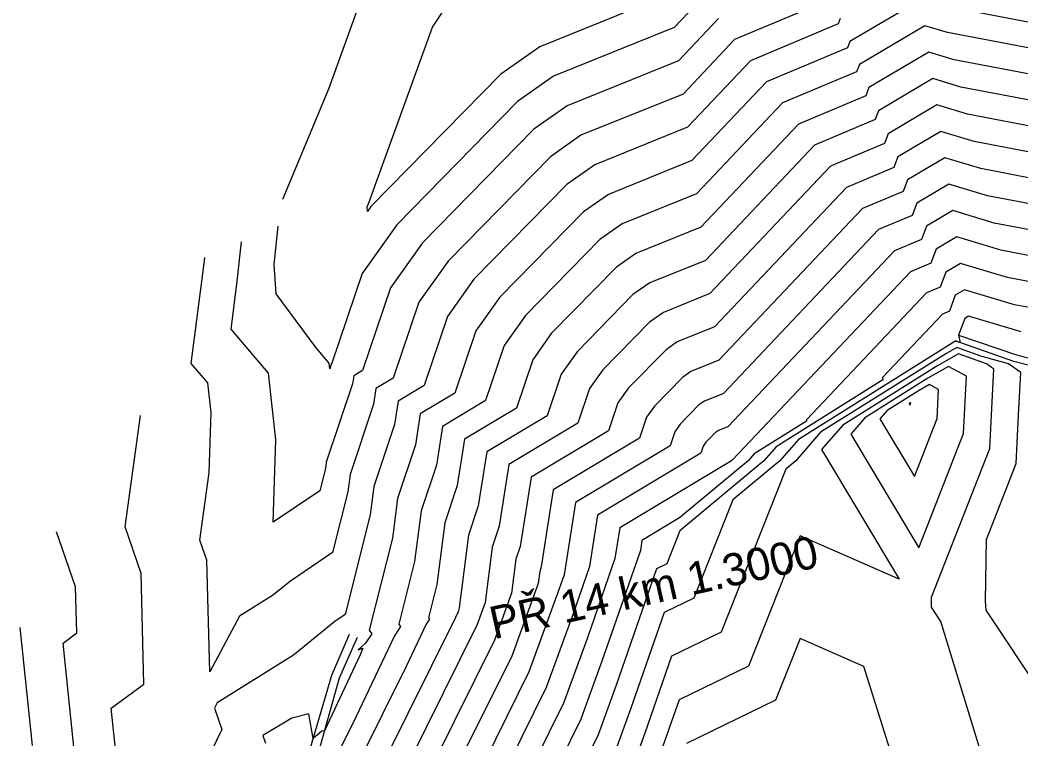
# Model space of a CAD drawing. Extents: x -549394 to -546608, y -1037055 to -1033629.
# Drawn here: x -548857.3 to -548577.2, y -1034124.2 to -1033923 of the extents above; entities that cross this region are included whole.
import ezdxf

# ---------------------------------------------------------------- set-up
doc = ezdxf.new("R2010")
doc.units = 0
for name, color, linetype in [('hlavni_vrst', 7, 'Continuous'), ('hrana_L', 7, 'Continuous'), ('norm_vrst', 7, 'Continuous'), ('x_popis_pricne_rezy_C21', 7, 'Continuous')]:
    doc.layers.add(name, color=color, linetype=linetype)

msp = doc.modelspace()

# ---------------------------------------------------------------- linework, layer by layer
at = {"layer": 'hlavni_vrst'}
for p, q in [((-548627.8, -1033922.53), (-548628.37, -1033924.06)), ((-548628.37, -1033924.06), (-548652.86, -1033934.37)), ((-548652.86, -1033934.37), (-548670.52, -1033953.01)), ((-548600.78, -1033946.76), (-548614.38, -1033954.83)), ((-548592.15, -1033949.35), (-548600.78, -1033946.76)), ((-548540.66, -1033959.22), (-548592.15, -1033949.35)), ((-548670.52, -1033953.01), (-548696.49, -1033963.52)), ((-548614.38, -1033954.83), (-548615.41, -1033957.58)), ((-548615.41, -1033957.58), (-548630.48, -1033963.92)), ((-548696.49, -1033963.52), (-548704.26, -1033968.98)), ((-548630.48, -1033963.92), (-548664.24, -1033999.57)), ((-548704.26, -1033968.98), (-548730.27, -1033995.53)), ((-548595.2, -1033983.71), (-548600.96, -1033987.12)), ((-548582.81, -1033987.44), (-548595.2, -1033983.71)), ((-548600.96, -1033987.12), (-548602.44, -1033991.09)), ((-548508.87, -1034001.61), (-548582.81, -1033987.44)), ((-548602.44, -1033991.09), (-548608.09, -1033993.47)), ((-548730.27, -1033995.53), (-548737.72, -1034006)), ((-548608.09, -1033993.47), (-548657.97, -1034046.13)), ((-548664.24, -1033999.57), (-548677.27, -1034004.84)), ((-548737.72, -1034006), (-548744.24, -1034025.33)), ((-548677.27, -1034004.84), (-548681.16, -1034007.58)), ((-548681.16, -1034007.58), (-548694.21, -1034020.89)), ((-548594.72, -1034016.44), (-548600.73, -1034019.84)), ((-548586.9, -1034019.27), (-548594.72, -1034016.44)), ((-548694.21, -1034020.89), (-548697.94, -1034026.14)), ((-548600.73, -1034019.84), (-548627.1, -1034036.36)), ((-548584.85, -1034020.69), (-548586.9, -1034019.27)), ((-548585.34, -1034031.77), (-548584.85, -1034020.69)), ((-548744.24, -1034025.33), (-548751.51, -1034029.69)), ((-548697.94, -1034026.14), (-548701.21, -1034035.84)), ((-548751.51, -1034029.69), (-548752.53, -1034036.21)), ((-548585.94, -1034042.9), (-548585.34, -1034031.77)), ((-548827.91, -1034064.82), (-548823.56, -1034033.65)), ((-548752.53, -1034036.21), (-548758.32, -1034053.57)), ((-548701.21, -1034035.84), (-548720.49, -1034047.4)), ((-548627.1, -1034036.36), (-548633.02, -1034043.25)), ((-548633.02, -1034043.25), (-548611.26, -1034079.53)), ((-548602.21, -1034084.51), (-548585.94, -1034042.9)), ((-548658.19, -1034046.35), (-548689.46, -1034065.1)), ((-548658.17, -1034046.29), (-548658.19, -1034046.35)), ((-548658.15, -1034046.26), (-548658.17, -1034046.29)), ((-548658.07, -1034046.18), (-548658.15, -1034046.26)), ((-548658.05, -1034046.16), (-548658.07, -1034046.18)), ((-548657.97, -1034046.13), (-548658.05, -1034046.16)), ((-548720.49, -1034047.4), (-548723.2, -1034064.67)), ((-548758.32, -1034053.57), (-548759.35, -1034061.54)), ((-548759.35, -1034061.54), (-548766.36, -1034089.43)), ((-548823.39, -1034077.91), (-548827.91, -1034064.82)), ((-548723.2, -1034064.67), (-548725.16, -1034070.55)), ((-548689.46, -1034065.1), (-548690.82, -1034073.74)), ((-548638.98, -1034067.36), (-548653.49, -1034103.86)), ((-548611.26, -1034079.53), (-548638.98, -1034067.36)), ((-548725.16, -1034070.55), (-548727.15, -1034086.06)), ((-548690.82, -1034073.74), (-548698.45, -1034095.69)), ((-548822.61, -1034108.85), (-548823.39, -1034077.91)), ((-548602.24, -1034087.01), (-548602.21, -1034084.51)), ((-548727.15, -1034086.06), (-548729.39, -1034092.21)), ((-548602.22, -1034087.38), (-548602.24, -1034087.01)), ((-548599.61, -1034091.31), (-548602.22, -1034087.38)), ((-548766.36, -1034089.43), (-548769.21, -1034091.35)), ((-548769.21, -1034091.35), (-548780.77, -1034100.82)), ((-548729.39, -1034092.21), (-548749.87, -1034133.46)), ((-548583.87, -1034143.01), (-548599.61, -1034091.31)), ((-548698.45, -1034095.69), (-548705.2, -1034114.25)), ((-548780.77, -1034100.82), (-548802.13, -1034114.16)), ((-548653.49, -1034103.86), (-548672.9, -1034113.25)), ((-548831.8, -1034115.63), (-548822.61, -1034108.85)), ((-548672.9, -1034113.25), (-548678.51, -1034129.39)), ((-548830.24, -1034130.51), (-548831.8, -1034115.63)), ((-548802.13, -1034114.16), (-548802.91, -1034115.6)), ((-548802.91, -1034115.6), (-548800.87, -1034121.57)), ((-548705.2, -1034114.25), (-548717.77, -1034139.57)), ((-548800.87, -1034121.57), (-548805.2, -1034130.59))]:
    msp.add_line(p, q, dxfattribs=at)
at = {"layer": 'hrana_L'}
for p, q in [((-548579.25, -1034018.6), (-548595.61, -1034012.8)), ((-548594.66, -1034011.2), (-548578.47, -1034016.69)), ((-548578.47, -1034016.69), (-548560.81, -1034021.29)), ((-548561.83, -1034023.04), (-548579.25, -1034018.6)), ((-548765.24, -1034094.98), (-548770.17, -1034106.46)), ((-548763, -1034095.87), (-548768.02, -1034107.25)), ((-548770.17, -1034106.46), (-548776.76, -1034129.09)), ((-548768.02, -1034107.25), (-548774.07, -1034128.86))]:
    msp.add_line(p, q, dxfattribs=at)
at = {"layer": 'norm_vrst'}
for p, q in [((-548770.93, -1033942.25), (-548761.43, -1033916.07)), ((-548741.85, -1033924.97), (-548736.86, -1033917.29)), ((-548675.54, -1033915.76), (-548711.87, -1033930.47)), ((-548666.3, -1033916.64), (-548674.29, -1033925.07)), ((-548630.97, -1033917.36), (-548657.34, -1033928.46)), ((-548605.25, -1033917.2), (-548625.12, -1033928.99)), ((-548566.09, -1033925.31), (-548599.62, -1033918.89)), ((-548661.82, -1033922.55), (-548673.03, -1033934.39)), ((-548759.67, -1033974.12), (-548741.85, -1033924.97)), ((-548674.29, -1033925.07), (-548708.03, -1033938.73)), ((-548604.13, -1033924.59), (-548622.43, -1033935.45)), ((-548597.75, -1033926.5), (-548604.13, -1033924.59)), ((-548657.34, -1033928.46), (-548671.78, -1033943.7)), ((-548559.73, -1033933.79), (-548597.75, -1033926.5)), ((-548711.87, -1033930.47), (-548722.73, -1033938.1)), ((-548625.78, -1033930.77), (-548648.39, -1033940.28)), ((-548625.12, -1033928.99), (-548625.78, -1033930.77)), ((-548673.03, -1033934.39), (-548704.18, -1033946.99)), ((-548603.01, -1033931.98), (-548619.75, -1033941.91)), ((-548595.89, -1033934.12), (-548603.01, -1033931.98)), ((-548553.37, -1033942.27), (-548595.89, -1033934.12)), ((-548622.43, -1033935.45), (-548623.19, -1033937.47)), ((-548722.73, -1033938.1), (-548759.11, -1033975.23)), ((-548708.03, -1033938.73), (-548718.11, -1033945.82)), ((-548623.19, -1033937.47), (-548643.91, -1033946.19)), ((-548601.9, -1033939.37), (-548617.07, -1033948.37)), ((-548594.02, -1033941.74), (-548601.9, -1033939.37)), ((-548783.78, -1033973.1), (-548770.93, -1033942.25)), ((-548648.39, -1033940.28), (-548669.27, -1033962.32)), ((-548619.75, -1033941.91), (-548620.59, -1033944.17)), ((-548547.01, -1033950.75), (-548594.02, -1033941.74)), ((-548671.78, -1033943.7), (-548700.34, -1033955.26)), ((-548620.59, -1033944.17), (-548639.43, -1033952.1)), ((-548718.11, -1033945.82), (-548751.9, -1033980.31)), ((-548704.18, -1033946.99), (-548713.49, -1033953.54)), ((-548643.91, -1033946.19), (-548668.01, -1033971.63)), ((-548617.07, -1033948.37), (-548618, -1033950.87)), ((-548618, -1033950.87), (-548634.96, -1033958.01)), ((-548713.49, -1033953.54), (-548744.69, -1033985.38)), ((-548639.43, -1033952.1), (-548666.75, -1033980.95)), ((-548700.34, -1033955.26), (-548708.87, -1033961.26)), ((-548599.67, -1033954.15), (-548611.7, -1033961.29)), ((-548590.28, -1033956.97), (-548599.67, -1033954.15)), ((-548634.96, -1033958.01), (-548665.5, -1033990.26)), ((-548534.3, -1033967.7), (-548590.28, -1033956.97)), ((-548708.87, -1033961.26), (-548737.48, -1033990.45)), ((-548669.27, -1033962.32), (-548692.65, -1033971.79)), ((-548611.7, -1033961.29), (-548612.81, -1033964.28)), ((-548598.55, -1033961.54), (-548609.01, -1033967.75)), ((-548588.41, -1033964.59), (-548598.55, -1033961.54)), ((-548612.81, -1033964.28), (-548626, -1033969.83)), ((-548527.94, -1033976.18), (-548588.41, -1033964.59)), ((-548609.01, -1033967.75), (-548610.22, -1033970.98)), ((-548626, -1033969.83), (-548662.99, -1034008.88)), ((-548597.44, -1033968.93), (-548606.33, -1033974.21)), ((-548586.54, -1033972.2), (-548597.44, -1033968.93)), ((-548692.65, -1033971.79), (-548699.64, -1033976.7)), ((-548668.01, -1033971.63), (-548688.8, -1033980.05)), ((-548610.22, -1033970.98), (-548621.52, -1033975.74)), ((-548521.58, -1033984.65), (-548586.54, -1033972.2)), ((-548760.14, -1033975.25), (-548759.67, -1033974.12)), ((-548760.04, -1033976.54), (-548760.14, -1033975.25)), ((-548759.11, -1033975.23), (-548760.04, -1033976.54)), ((-548621.52, -1033975.74), (-548661.73, -1034018.19)), ((-548606.33, -1033974.21), (-548607.63, -1033977.69)), ((-548596.32, -1033976.32), (-548603.65, -1033980.67)), ((-548584.67, -1033979.82), (-548596.32, -1033976.32)), ((-548699.64, -1033976.7), (-548723.05, -1034000.6)), ((-548607.63, -1033977.69), (-548617.05, -1033981.65)), ((-548786.2, -1033991.45), (-548785.02, -1033980.7)), ((-548751.9, -1033980.31), (-548761.58, -1033993.91)), ((-548688.8, -1033980.05), (-548695.02, -1033984.42)), ((-548666.75, -1033980.95), (-548684.96, -1033988.31)), ((-548617.05, -1033981.65), (-548660.48, -1034027.51)), ((-548603.65, -1033980.67), (-548605.03, -1033984.39)), ((-548515.22, -1033993.13), (-548584.67, -1033979.82)), ((-548695.02, -1033984.42), (-548715.84, -1034005.67)), ((-548605.03, -1033984.39), (-548612.57, -1033987.56)), ((-548796.62, -1033996.93), (-548795.32, -1033985.1)), ((-548744.69, -1033985.38), (-548753.63, -1033997.94)), ((-548612.57, -1033987.56), (-548659.22, -1034036.82)), ((-548805.97, -1033992.57), (-548805.63, -1033989.5)), ((-548737.48, -1033990.45), (-548745.67, -1034001.97)), ((-548684.96, -1033988.31), (-548690.4, -1033992.14)), ((-548665.5, -1033990.26), (-548681.11, -1033996.58)), ((-548809.39, -1034019.11), (-548805.97, -1033992.57)), ((-548785.58, -1033999.63), (-548786.2, -1033991.45)), ((-548690.4, -1033992.14), (-548708.63, -1034010.74)), ((-548594.09, -1033991.1), (-548598.28, -1033993.58)), ((-548580.94, -1033995.05), (-548594.09, -1033991.1)), ((-548761.58, -1033993.91), (-548770.05, -1034019.02)), ((-548598.28, -1033993.58), (-548599.85, -1033997.79)), ((-548526.36, -1034005.51), (-548580.94, -1033995.05)), ((-548798.24, -1034009.5), (-548796.62, -1033996.93)), ((-548753.63, -1033997.94), (-548761.45, -1034021.12)), ((-548681.11, -1033996.58), (-548685.78, -1033999.86)), ((-548599.85, -1033997.79), (-548603.61, -1033999.38)), ((-548592.97, -1033998.49), (-548595.59, -1034000.04)), ((-548579.07, -1034002.67), (-548592.97, -1033998.49)), ((-548774.44, -1034014.78), (-548785.58, -1033999.63)), ((-548723.05, -1034000.6), (-548729.76, -1034010.03)), ((-548685.78, -1033999.86), (-548701.42, -1034015.82)), ((-548603.61, -1033999.38), (-548637.27, -1034034.91)), ((-548595.59, -1034000.04), (-548597.25, -1034004.5)), ((-548745.67, -1034001.97), (-548752.84, -1034023.23)), ((-548547.43, -1034008.73), (-548579.07, -1034002.67)), ((-548715.84, -1034005.67), (-548721.81, -1034014.06)), ((-548599.14, -1034005.29), (-548615.96, -1034023.06)), ((-548597.25, -1034004.5), (-548599.14, -1034005.29)), ((-548592.91, -1034006.5), (-548594.66, -1034011.2)), ((-548591.86, -1034005.88), (-548592.91, -1034006.5)), ((-548577.2, -1034010.29), (-548591.86, -1034005.88)), ((-548787.78, -1034021.81), (-548798.24, -1034009.5)), ((-548729.76, -1034010.03), (-548735.63, -1034027.43)), ((-548662.99, -1034008.88), (-548673.42, -1034013.11)), ((-548708.63, -1034010.74), (-548713.85, -1034018.09)), ((-548594.66, -1034011.2), (-548594.27, -1034013.28)), ((-548594.66, -1034011.2), (-548594.66, -1034011.2)), ((-548594.66, -1034011.2), (-548594.66, -1034011.2)), ((-548594.66, -1034011.2), (-548594.66, -1034011.2)), ((-548594.66, -1034011.2), (-548594.66, -1034011.2)), ((-548594.66, -1034011.2), (-548594.66, -1034011.2)), ((-548770.82, -1034019.04), (-548774.44, -1034014.78)), ((-548721.81, -1034014.06), (-548727.03, -1034029.53)), ((-548676.54, -1034015.3), (-548686.99, -1034025.96)), ((-548673.42, -1034013.11), (-548676.54, -1034015.3)), ((-548595.73, -1034012.97), (-548639.5, -1034040.41)), ((-548595.15, -1034014.66), (-548598.23, -1034016.4)), ((-548595.59, -1034012.89), (-548595.73, -1034012.97)), ((-548595.27, -1034013), (-548595.59, -1034012.89)), ((-548594.27, -1034013.28), (-548595.27, -1034013)), ((-548588.48, -1034017.08), (-548595.15, -1034014.66)), ((-548713.85, -1034018.09), (-548718.42, -1034031.63)), ((-548701.42, -1034015.82), (-548705.9, -1034022.11)), ((-548661.73, -1034018.19), (-548669.58, -1034021.37)), ((-548598.23, -1034016.4), (-548633.3, -1034038.39)), ((-548580.67, -1034019.2), (-548588.48, -1034017.08)), ((-548804.74, -1034024.58), (-548809.39, -1034019.11)), ((-548770.64, -1034020.65), (-548770.82, -1034019.04)), ((-548770.13, -1034019.13), (-548770.64, -1034020.65)), ((-548770.12, -1034019.07), (-548770.13, -1034019.13)), ((-548770.05, -1034019.02), (-548770.12, -1034019.07)), ((-548761.45, -1034021.12), (-548763.92, -1034022.61)), ((-548597.46, -1034020.01), (-548603.23, -1034023.27)), ((-548592.46, -1034022.69), (-548597.46, -1034020.01)), ((-548577.22, -1034021.65), (-548580.67, -1034019.2)), ((-548785.7, -1034040.5), (-548787.78, -1034021.81)), ((-548763.92, -1034022.61), (-548764.27, -1034024.82)), ((-548752.84, -1034023.23), (-548757.71, -1034026.15)), ((-548705.9, -1034022.11), (-548709.82, -1034033.74)), ((-548671.92, -1034023.02), (-548679.78, -1034031.04)), ((-548669.58, -1034021.37), (-548671.92, -1034023.02)), ((-548615.89, -1034023.73), (-548645.71, -1034042.43)), ((-548603.23, -1034023.27), (-548620.89, -1034034.34)), ((-548615.96, -1034023.06), (-548615.89, -1034023.73)), ((-548593.32, -1034038.72), (-548592.46, -1034022.69)), ((-548577.91, -1034033.56), (-548577.22, -1034021.65)), ((-548803.82, -1034032.89), (-548804.74, -1034024.58)), ((-548764.27, -1034024.82), (-548771.59, -1034046.78)), ((-548757.71, -1034026.15), (-548758.4, -1034030.52)), ((-548686.99, -1034025.96), (-548689.99, -1034030.17)), ((-548605.73, -1034026.7), (-548614.69, -1034032.32)), ((-548602.8, -1034025.05), (-548605.73, -1034026.7)), ((-548600.26, -1034026.41), (-548602.8, -1034025.05)), ((-548600.7, -1034034.54), (-548600.26, -1034026.41)), ((-548735.63, -1034027.43), (-548745.31, -1034033.23)), ((-548727.03, -1034029.53), (-548739.1, -1034036.77)), ((-548665.73, -1034029.63), (-548667.31, -1034030.74)), ((-548660.48, -1034027.51), (-548665.73, -1034029.63)), ((-548758.4, -1034030.52), (-548764.96, -1034050.17)), ((-548718.42, -1034031.63), (-548732.9, -1034040.31)), ((-548689.99, -1034030.17), (-548692.61, -1034037.94)), ((-548679.78, -1034031.04), (-548682.03, -1034034.2)), ((-548667.31, -1034030.74), (-548672.57, -1034036.11)), ((-548614.69, -1034032.32), (-548616.7, -1034034.66)), ((-548608.49, -1034030.3), (-548608.54, -1034030.37)), ((-548608.54, -1034030.37), (-548608.26, -1034030.84)), ((-548608.23, -1034030.14), (-548608.49, -1034030.3)), ((-548608.26, -1034030.84), (-548608.08, -1034030.37)), ((-548608.14, -1034030.09), (-548608.23, -1034030.14)), ((-548608.07, -1034030.13), (-548608.14, -1034030.09)), ((-548608.08, -1034030.37), (-548608.07, -1034030.13)), ((-548804.34, -1034049.67), (-548803.82, -1034032.89)), ((-548745.31, -1034033.23), (-548746.67, -1034041.9)), ((-548709.82, -1034033.74), (-548726.69, -1034043.86)), ((-548682.03, -1034034.2), (-548684, -1034040.04)), ((-548637.23, -1034035.25), (-548651.91, -1034044.45)), ((-548637.27, -1034034.91), (-548637.23, -1034035.25)), ((-548620.89, -1034034.34), (-548624.86, -1034038.95)), ((-548616.7, -1034034.66), (-548607.04, -1034050.77)), ((-548607.04, -1034050.77), (-548600.7, -1034034.54)), ((-548578.25, -1034041.38), (-548577.91, -1034033.56)), ((-548739.1, -1034036.77), (-548740.8, -1034047.59)), ((-548692.61, -1034037.94), (-548714.28, -1034050.94)), ((-548672.57, -1034036.11), (-548674.08, -1034038.23)), ((-548661.89, -1034037.9), (-548662.69, -1034038.46)), ((-548659.22, -1034036.82), (-548661.89, -1034037.9)), ((-548786.42, -1034063.53), (-548785.7, -1034040.5)), ((-548732.9, -1034040.31), (-548734.93, -1034053.28)), ((-548684, -1034040.04), (-548708.08, -1034054.48)), ((-548674.08, -1034038.23), (-548675.4, -1034042.14)), ((-548662.69, -1034038.46), (-548665.36, -1034041.18)), ((-548639.5, -1034040.41), (-548644.65, -1034046.39)), ((-548633.3, -1034038.39), (-548640.18, -1034046.38)), ((-548624.86, -1034038.95), (-548605.82, -1034070.71)), ((-548605.82, -1034070.71), (-548593.32, -1034038.72)), ((-548746.67, -1034041.9), (-548751.69, -1034056.96)), ((-548675.4, -1034042.14), (-548701.87, -1034058.02)), ((-548666.12, -1034042.26), (-548666.79, -1034044.25)), ((-548665.36, -1034041.18), (-548666.12, -1034042.26)), ((-548645.71, -1034042.43), (-548649.12, -1034046.4)), ((-548578.56, -1034047.08), (-548578.25, -1034041.38)), ((-548726.69, -1034043.86), (-548729.07, -1034058.98)), ((-548666.79, -1034044.25), (-548695.67, -1034061.56)), ((-548653.59, -1034046.4), (-548672.74, -1034062.34)), ((-548649.12, -1034046.4), (-548672.65, -1034065.98)), ((-548644.65, -1034046.39), (-548657.81, -1034057.34)), ((-548651.91, -1034044.45), (-548653.59, -1034046.4)), ((-548640.18, -1034046.38), (-548642.98, -1034048.71)), ((-548771.82, -1034048.54), (-548773.37, -1034054.73)), ((-548771.59, -1034046.78), (-548771.82, -1034048.54)), ((-548740.8, -1034047.59), (-548745.06, -1034060.36)), ((-548642.98, -1034048.71), (-548661.11, -1034094.32)), ((-548586.89, -1034068.39), (-548578.56, -1034047.08)), ((-548806.98, -1034068.56), (-548804.34, -1034049.67)), ((-548764.96, -1034050.17), (-548765.58, -1034055.04)), ((-548714.28, -1034050.94), (-548717.33, -1034070.36)), ((-548773.37, -1034054.73), (-548786.42, -1034063.53)), ((-548734.93, -1034053.28), (-548738.43, -1034063.75)), ((-548708.08, -1034054.48), (-548711.47, -1034076.05)), ((-548765.58, -1034055.04), (-548769.87, -1034072.08)), ((-548751.69, -1034056.96), (-548753.11, -1034068.04)), ((-548657.81, -1034057.34), (-548668.72, -1034084.78)), ((-548745.06, -1034060.36), (-548746.88, -1034074.54)), ((-548729.07, -1034058.98), (-548731.79, -1034067.15)), ((-548701.87, -1034058.02), (-548705.05, -1034078.25)), ((-548695.67, -1034061.56), (-548697.94, -1034075.99)), ((-548672.74, -1034062.34), (-548683.26, -1034068.64)), ((-548738.43, -1034063.75), (-548740.64, -1034081.04)), ((-548672.65, -1034065.98), (-548676.34, -1034075.24)), ((-548841.76, -1034081.61), (-548847.06, -1034066.26)), ((-548805.03, -1034074.21), (-548806.98, -1034068.56)), ((-548753.11, -1034068.04), (-548759.59, -1034093.8)), ((-548731.79, -1034067.15), (-548734.41, -1034087.54)), ((-548683.26, -1034068.64), (-548683.71, -1034071.48)), ((-548587.15, -1034085.62), (-548586.89, -1034068.39)), ((-548717.33, -1034070.36), (-548718.53, -1034073.94)), ((-548683.71, -1034071.48), (-548694.46, -1034102.43)), ((-548804.23, -1034105.43), (-548805.03, -1034074.21)), ((-548769.87, -1034072.08), (-548781.63, -1034080.02)), ((-548718.53, -1034073.94), (-548719.74, -1034083.4)), ((-548746.88, -1034074.54), (-548751.29, -1034092.07)), ((-548711.47, -1034076.05), (-548711.89, -1034077.34)), ((-548697.94, -1034075.99), (-548702.44, -1034088.95)), ((-548679.16, -1034076.61), (-548690.47, -1034109.17)), ((-548676.34, -1034075.24), (-548679.16, -1034076.61)), ((-548781.63, -1034080.02), (-548786.62, -1034084.1)), ((-548711.89, -1034077.34), (-548712.33, -1034080.73)), ((-548705.05, -1034078.25), (-548706.43, -1034082.21)), ((-548841.43, -1034094.56), (-548841.76, -1034081.61)), ((-548740.64, -1034081.04), (-548742.98, -1034090.34)), ((-548712.33, -1034080.73), (-548719.72, -1034101.03)), ((-548706.43, -1034082.21), (-548714.88, -1034105.43)), ((-548786.62, -1034084.1), (-548795.84, -1034089.86)), ((-548719.74, -1034083.4), (-548724.55, -1034096.62)), ((-548668.72, -1034084.78), (-548677.07, -1034088.82)), ((-548586.99, -1034088.17), (-548587.15, -1034085.62)), ((-548734.41, -1034087.54), (-548734.68, -1034088.61)), ((-548569.05, -1034115.21), (-548586.99, -1034088.17)), ((-548795.84, -1034089.86), (-548804.23, -1034105.43)), ((-548735.41, -1034090.19), (-548756.29, -1034132.24)), ((-548742.73, -1034090.71), (-548743.65, -1034092.09)), ((-548742.98, -1034090.34), (-548742.73, -1034090.71)), ((-548734.76, -1034088.81), (-548735.41, -1034090.19)), ((-548734.65, -1034088.65), (-548734.76, -1034088.81)), ((-548734.68, -1034088.61), (-548734.65, -1034088.65)), ((-548702.44, -1034088.95), (-548710.04, -1034109.84)), ((-548677.07, -1034088.82), (-548686.48, -1034115.91)), ((-548853.84, -1034126.05), (-548857.3, -1034093.07)), ((-548759.59, -1034093.8), (-548758.88, -1034094.82)), ((-548750.8, -1034092.76), (-548752.55, -1034095.38)), ((-548751.29, -1034092.07), (-548750.8, -1034092.76)), ((-548743.65, -1034092.09), (-548749.37, -1034104.15)), ((-548845.27, -1034097.4), (-548841.43, -1034094.56)), ((-548752.55, -1034095.38), (-548763.32, -1034118.11)), ((-548758.88, -1034094.82), (-548760.61, -1034097.41)), ((-548724.55, -1034096.62), (-548743.45, -1034134.69)), ((-548661.11, -1034094.32), (-548674.98, -1034101.04)), ((-548639, -1034096.11), (-548645.87, -1034113.4)), ((-548621.22, -1034103.91), (-548639, -1034096.11)), ((-548842.04, -1034128.28), (-548845.27, -1034097.4)), ((-548760.62, -1034097.41), (-548762.66, -1034099.32)), ((-548762.66, -1034099.32), (-548761.36, -1034098.81)), ((-548762.66, -1034099.32), (-548762.66, -1034099.32)), ((-548761.36, -1034098.81), (-548762.09, -1034100.69)), ((-548761.36, -1034098.81), (-548761.36, -1034098.81)), ((-548760.62, -1034097.41), (-548760.61, -1034097.41)), ((-548762.09, -1034100.69), (-548772.14, -1034121.96)), ((-548719.72, -1034101.03), (-548737.03, -1034135.91)), ((-548694.46, -1034102.43), (-548700.36, -1034118.65)), ((-548674.98, -1034101.04), (-548682.49, -1034122.65)), ((-548749.37, -1034104.15), (-548762.71, -1034131.02)), ((-548609.42, -1034141.28), (-548621.22, -1034103.91)), ((-548714.88, -1034105.43), (-548730.61, -1034137.13)), ((-548710.04, -1034109.84), (-548724.19, -1034138.35)), ((-548690.47, -1034109.17), (-548695.53, -1034123.06)), ((-548645.87, -1034113.4), (-548670.81, -1034125.46)), ((-548686.48, -1034115.91), (-548690.69, -1034127.47)), ((-548781.24, -1034118.42), (-548789.39, -1034123.23)), ((-548776.52, -1034117.22), (-548781.24, -1034118.42)), ((-548775.31, -1034124.1), (-548776.52, -1034117.22)), ((-548763.32, -1034118.11), (-548769.13, -1034129.8)), ((-548700.36, -1034118.65), (-548711.35, -1034140.79)), ((-548772.89, -1034122.08), (-548775.31, -1034124.1)), ((-548772.14, -1034121.96), (-548772.89, -1034122.08)), ((-548789.39, -1034123.23), (-548788.64, -1034125.44)), ((-548695.53, -1034123.06), (-548704.93, -1034142.01)), ((-548682.49, -1034122.65), (-548685.85, -1034131.87))]:
    msp.add_line(p, q, dxfattribs=at)

# ---------------------------------------------------------------- texts
at = {"layer": 'x_popis_pricne_rezy_C21'}
msp.add_text('PŘ 14 km 1.3000', height=9.0627, rotation=12.5402, dxfattribs=at).set_placement((-548724.71, -1034096.34))

doc.saveas('drawing.dxf')
